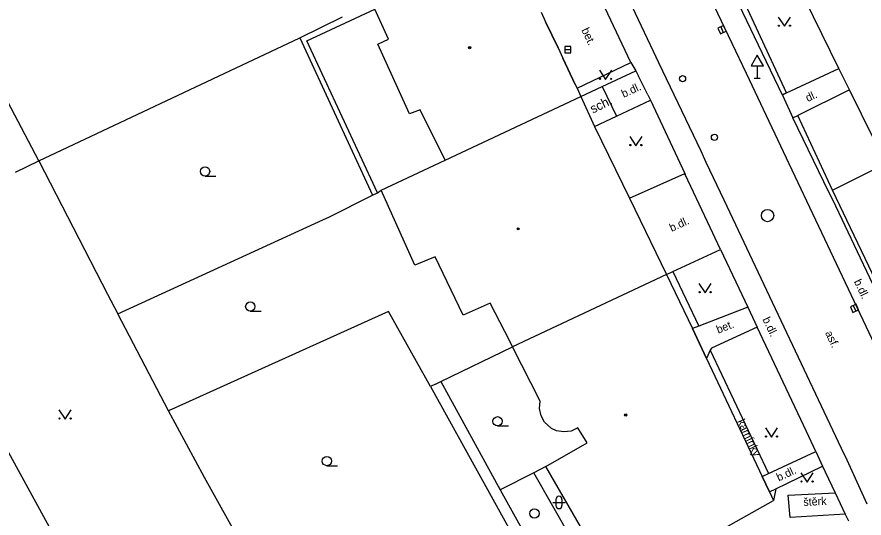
# Model space of a CAD drawing. Extents: x -600391 to -599491, y -1160176 to -1159402.
# Drawn here: x -600232.8 to -600164, y -1159825.7 to -1159785 of the extents above; entities that cross this region are included whole.
import ezdxf

# ---------------------------------------------------------------- set-up
doc = ezdxf.new("R2010")
doc.units = 0
for name, color, linetype in [('Level 10', 7, 'Continuous'), ('Level 11', 7, 'Continuous'), ('Level 27', 7, 'Continuous'), ('Level 28', 7, 'Continuous'), ('Level 34', 7, 'Continuous'), ('Level 36', 7, 'Continuous'), ('Level 39', 7, 'Continuous'), ('Level 40', 7, 'Continuous'), ('Level 42', 7, 'Continuous'), ('Level 5', 7, 'Continuous'), ('Level 51', 7, 'Continuous'), ('Level 6', 7, 'Continuous'), ('Level 7', 7, 'Continuous'), ('Level 8', 7, 'Continuous')]:
    doc.layers.add(name, color=color, linetype=linetype)

msp = doc.modelspace()

# ---------------------------------------------------------------- linework, layer by layer
at = {"layer": 'Level 10'}
for points in [[(-600207.08, -1159733.09), (-600204.09, -1159739.42), (-600203.67, -1159740.35), (-600201.73, -1159744.4), (-600201.28, -1159745.31), (-600193.16, -1159762.47), (-600192.72, -1159763.39), (-600190.15, -1159768.81), (-600189.71, -1159769.71), (-600181.16, -1159787.79), (-600180.73, -1159788.7), (-600177.31, -1159795.87), (-600176.88, -1159796.81), (-600175.437, -1159799.852), (-600174.02, -1159802.84), (-600173.59, -1159803.76), (-600165.9, -1159820.02), (-600165.45, -1159820.96), (-600163.81, -1159824.53)], [(-600158.72, -1159821.06), (-600159.95, -1159818.426), (-600160.27, -1159817.74), (-600169.89, -1159797.44), (-600171.51, -1159794.02), (-600173.6, -1159789.61), (-600177.09, -1159782.26), (-600180.56, -1159774.92), (-600184.38, -1159766.92), (-600187.61, -1159760.14), (-600188.03, -1159759.22), (-600189.21, -1159756.74), (-600189.62, -1159755.83), (-600193.78, -1159747.07), (-600194.22, -1159746.13), (-600195.79, -1159742.84), (-600196.2, -1159741.93), (-600197.21, -1159739.84), (-600197.66, -1159738.93), (-600199.99, -1159733.97)]]:
    msp.add_lwpolyline(points, dxfattribs=at)
at = {"layer": 'Level 11'}
for points in [[(-600182.98, -1159788.7), (-600185.54, -1159783.24)], [(-600187.35, -1159790.8), (-600182.98, -1159788.7)], [(-600170.34, -1159791.18), (-600166.08, -1159789.19)], [(-600185.3, -1159790.66), (-600184.14, -1159793.07)], [(-600165.23, -1159790.93), (-600169.43, -1159793)], [(-600184.14, -1159793.07), (-600181.39, -1159791.77)], [(-600185.92, -1159793.91), (-600184.14, -1159793.07)], [(-600183.09, -1159799.71), (-600178.6, -1159797.73)], [(-600175.69, -1159803.88), (-600176.76, -1159801.63), (-600178.57, -1159797.81)], [(-600175.69, -1159803.88), (-600173.49, -1159808.57)], [(-600179.56, -1159805.67), (-600177.46, -1159810.11)], [(-600173.49, -1159808.57), (-600177.46, -1159810.11), (-600177.98, -1159810.31)], [(-600173.49, -1159808.57), (-600172.72, -1159810.19)], [(-600172.72, -1159810.19), (-600176.44, -1159811.9), (-600176.53, -1159812.07), (-600176.85, -1159812.73)], [(-600167.97, -1159820.27), (-600168.72, -1159818.65), (-600172.72, -1159810.19)], [(-600176.53, -1159812.07), (-600171.8, -1159822.07)], [(-600172.32, -1159822.31), (-600171.8, -1159822.07), (-600167.97, -1159820.27)], [(-600167.97, -1159820.27), (-600167.43, -1159821.46)], [(-600171.73, -1159823.56), (-600171.21, -1159823.31), (-600167.43, -1159821.46)], [(-600167.43, -1159821.46), (-600167.2, -1159821.94), (-600166.39, -1159823.64), (-600165.58, -1159825.36), (-600165.31, -1159825.92)], [(-600171.21, -1159823.31), (-600171.4, -1159824.25)], [(-600165.58, -1159825.36), (-600170.04, -1159825.64), (-600170.2, -1159823.82), (-600166.39, -1159823.64)]]:
    msp.add_lwpolyline(points, dxfattribs=at)
at = {"layer": 'Level 27'}
for p, q in [((-600175.684, -1159785.813), (-600175.476, -1159786.267)), ((-600188.34, -1159787.66), (-600187.84, -1159787.66)), ((-600164.917, -1159808.43), (-600164.723, -1159808.89))]:
    msp.add_line(p, q, dxfattribs=at)
for points in [[(-600175.911, -1159785.917), (-600175.703, -1159786.371), (-600175.249, -1159786.163), (-600175.457, -1159785.709)], [(-600188.34, -1159787.91), (-600187.84, -1159787.91), (-600187.84, -1159787.41), (-600188.34, -1159787.41)], [(-600165.148, -1159808.527), (-600164.953, -1159808.988), (-600164.492, -1159808.793), (-600164.687, -1159808.332)]]:
    msp.add_lwpolyline(points, close=True, dxfattribs=at)
msp.add_circle((-600171.88, -1159801.13), 0.5, dxfattribs=at)
at = {"layer": 'Level 28'}
for centre in [(-600178.78, -1159790.02), (-600176.19, -1159794.78)]:
    msp.add_circle(centre, 0.25, dxfattribs=at)
at = {"layer": 'Level 34'}
for p, q in [((-600172.72, -1159788.972), (-600172.72, -1159789.99)), ((-600172.97, -1159789.99), (-600172.47, -1159789.99))]:
    msp.add_line(p, q, dxfattribs=at)
msp.add_lwpolyline([(-600173.22, -1159788.972), (-600172.22, -1159788.972), (-600172.72, -1159788.106)], close=True, dxfattribs=at)
at = {"layer": 'Level 36'}
for p, q in [((-600217.55, -1159797.925), (-600216.675, -1159797.925)), ((-600213.88, -1159808.895), (-600213.005, -1159808.895)), ((-600193.8, -1159818.205), (-600192.925, -1159818.205)), ((-600207.66, -1159821.435), (-600206.785, -1159821.435)), ((-600189.326, -1159824.416), (-600188.326, -1159824.416)), ((-600189.076, -1159824.166), (-600189.076, -1159824.666)), ((-600188.576, -1159824.166), (-600188.576, -1159824.666))]:
    msp.add_line(p, q, dxfattribs=at)
for points in [[(-600171.01, -1159785.02), (-600170.51, -1159785.77), (-600170.01, -1159785.02)], [(-600185.53, -1159789.33), (-600185.03, -1159790.08), (-600184.53, -1159789.33)], [(-600183.07, -1159794.71), (-600182.57, -1159795.46), (-600182.07, -1159794.71)], [(-600177.45, -1159806.65), (-600176.95, -1159807.4), (-600176.45, -1159806.65)], [(-600229.42, -1159816.9), (-600228.92, -1159817.65), (-600228.42, -1159816.9)], [(-600172.06, -1159818.37), (-600171.56, -1159819.12), (-600171.06, -1159818.37)], [(-600169.17, -1159822.02), (-600168.67, -1159822.77), (-600168.17, -1159822.02)]]:
    msp.add_lwpolyline(points, dxfattribs=at)
for centre, radius in [((-600170.96, -1159785.72), 0.05), ((-600170.061, -1159785.72), 0.05), ((-600185.48, -1159790.03), 0.05), ((-600184.581, -1159790.03), 0.05), ((-600183.02, -1159795.41), 0.05), ((-600182.121, -1159795.41), 0.05), ((-600217.55, -1159797.55), 0.375), ((-600177.4, -1159807.35), 0.05), ((-600176.501, -1159807.35), 0.05), ((-600213.88, -1159808.52), 0.375), ((-600229.37, -1159817.6), 0.05), ((-600228.471, -1159817.6), 0.05), ((-600193.8, -1159817.83), 0.375), ((-600172.01, -1159819.07), 0.05), ((-600171.111, -1159819.07), 0.05), ((-600207.66, -1159821.06), 0.375), ((-600169.12, -1159822.72), 0.05), ((-600168.221, -1159822.72), 0.05), ((-600190.81, -1159825.31), 0.375)]:
    msp.add_circle(centre, radius, dxfattribs=at)
for centre, start, end in [((-600188.826, -1159824.166), 0, 180), ((-600188.826, -1159824.666), 180, 0)]:
    msp.add_arc(centre, 0.25, start, end, dxfattribs=at)
at = {"layer": 'Level 39'}
for centre, radius in [((-600196.07, -1159787.5), 0.09), ((-600196.07, -1159787.5), 0.0398), ((-600192.13, -1159802.21), 0.09), ((-600192.13, -1159802.21), 0.0398), ((-600183.4, -1159817.32), 0.09), ((-600183.4, -1159817.32), 0.0398)]:
    msp.add_circle(centre, radius, dxfattribs=at)
at = {"layer": 'Level 5'}
for points in [[(-600166.08, -1159789.19), (-600170.89, -1159779.39)], [(-600202.67, -1159786.81), (-600203.77, -1159784.37)], [(-600190.27, -1159784.63), (-600189.9, -1159785.41)], [(-600189.9, -1159785.41), (-600188.89, -1159787.51)], [(-600203.52, -1159787.22), (-600202.67, -1159786.81)], [(-600200.94, -1159792.88), (-600203.52, -1159787.22)], [(-600188.89, -1159787.51), (-600188.51, -1159788.36)], [(-600188.51, -1159788.36), (-600187.49, -1159790.5)], [(-600165.23, -1159790.93), (-600166.08, -1159789.19)], [(-600187.49, -1159790.5), (-600187.35, -1159790.8)], [(-600187.35, -1159790.8), (-600187.04, -1159791.48)], [(-600198.06, -1159796.64), (-600187.04, -1159791.48)], [(-600187.04, -1159791.48), (-600185.92, -1159793.91)], [(-600162.28, -1159796.91), (-600165.23, -1159790.93)], [(-600200.09, -1159792.55), (-600200.94, -1159792.88)], [(-600198.06, -1159796.64), (-600200.09, -1159792.55)], [(-600185.92, -1159793.91), (-600183.09, -1159799.71)], [(-600203.26, -1159799.07), (-600198.06, -1159796.64)], [(-600200.52, -1159805.15), (-600203.26, -1159799.07)], [(-600183.09, -1159799.71), (-600180.09, -1159805.92)], [(-600198.88, -1159804.48), (-600200.52, -1159805.15)], [(-600196.59, -1159809.23), (-600198.88, -1159804.48)], [(-600180.09, -1159805.92), (-600192.58, -1159811.78)], [(-600180.09, -1159805.92), (-600177.98, -1159810.31)], [(-600194.39, -1159808.23), (-600196.59, -1159809.23)], [(-600192.81, -1159811.33), (-600194.39, -1159808.23)], [(-600177.98, -1159810.31), (-600176.85, -1159812.73)], [(-600192.58, -1159811.78), (-600192.81, -1159811.33)], [(-600190.33, -1159816.2), (-600192.58, -1159811.78)], [(-600176.85, -1159812.73), (-600172.32, -1159822.31)], [(-600190.39, -1159816.8), (-600190.33, -1159816.2)], [(-600190.27, -1159817.39), (-600190.39, -1159816.8)], [(-600189.98, -1159817.91), (-600190.27, -1159817.39)], [(-600189.43, -1159818.41), (-600189.98, -1159817.91)], [(-600189.01, -1159818.6), (-600189.43, -1159818.41)], [(-600187.28, -1159818.36), (-600187.82, -1159818.62)], [(-600186.52, -1159819.58), (-600187.28, -1159818.36)], [(-600188.42, -1159818.7), (-600189.01, -1159818.6)], [(-600187.82, -1159818.62), (-600188.42, -1159818.7)], [(-600189.89, -1159821.5), (-600186.52, -1159819.58)], [(-600184.14, -1159831.42), (-600189.89, -1159821.5)], [(-600172.32, -1159822.31), (-600171.73, -1159823.56)], [(-600171.73, -1159823.56), (-600171.4, -1159824.25)], [(-600184.14, -1159831.42), (-600171.4, -1159824.25)]]:
    msp.add_lwpolyline(points, dxfattribs=at)
at = {"layer": 'Level 51'}
for points in [[(-600231.06, -1159796.68), (-600238.9, -1159781.79)], [(-600209.28, -1159786.95), (-600203.77, -1159784.37)], [(-600209.86, -1159786.71), (-600206.39, -1159785)], [(-600231.06, -1159796.68), (-600209.86, -1159786.71)], [(-600209.86, -1159786.71), (-600203.96, -1159799.47)], [(-600203.54, -1159799.29), (-600209.28, -1159786.95)], [(-600232.95, -1159797.62), (-600231.06, -1159796.68)], [(-600231.06, -1159796.68), (-600225.47, -1159807.52)], [(-600203.54, -1159799.29), (-600203.26, -1159799.07)], [(-600207.44, -1159801.23), (-600203.96, -1159799.47)], [(-600203.96, -1159799.47), (-600203.54, -1159799.29)], [(-600224.63, -1159809.1), (-600208, -1159801.49)], [(-600208, -1159801.49), (-600207.44, -1159801.23)], [(-600225.47, -1159807.52), (-600224.63, -1159809.1)], [(-600220.53, -1159816.97), (-600224.63, -1159809.1)], [(-600202.67, -1159808.93), (-600220.53, -1159816.97)], [(-600199.25, -1159815.01), (-600202.67, -1159808.93)], [(-600198.42, -1159814.6), (-600192.58, -1159811.78)], [(-600228.91, -1159828.75), (-600236.99, -1159814.01)], [(-600198.85, -1159814.83), (-600199.25, -1159815.01)], [(-600198.85, -1159814.83), (-600198.42, -1159814.6)], [(-600198.42, -1159814.6), (-600193.6, -1159823.39)], [(-600199.25, -1159815.01), (-600190.53, -1159830.76)], [(-600217.61, -1159822.39), (-600220.53, -1159816.97)], [(-600189.89, -1159821.5), (-600190.85, -1159822.02)], [(-600211.3, -1159833.74), (-600217.61, -1159822.39)], [(-600190.85, -1159822.02), (-600193.6, -1159823.39)], [(-600187.78, -1159827.42), (-600190.85, -1159822.02)], [(-600193.6, -1159823.39), (-600190.5, -1159828.94)]]:
    msp.add_lwpolyline(points, dxfattribs=at)
at = {"layer": 'Level 6'}
for points in [[(-600188.89, -1159787.51), (-600189.9, -1159785.41)], [(-600187.49, -1159790.5), (-600188.51, -1159788.36)], [(-600176.85, -1159812.73), (-600177.98, -1159810.31)], [(-600171.73, -1159823.56), (-600172.32, -1159822.31)]]:
    msp.add_lwpolyline(points, dxfattribs=at)
at = {"layer": 'Level 7'}
for points in [[(-600170.34, -1159791.18), (-600174.9, -1159781.36), (-600173.01, -1159780.43)], [(-600170.34, -1159791.18), (-600170.67, -1159791.35), (-600175.52, -1159781.23)], [(-600182.98, -1159788.7), (-600182.58, -1159789.38)], [(-600185.3, -1159790.66), (-600182.58, -1159789.38)], [(-600182.58, -1159789.38), (-600182.36, -1159789.81)], [(-600187.04, -1159791.48), (-600185.3, -1159790.66)], [(-600181.6, -1159791.33), (-600181.39, -1159791.77)], [(-600181.39, -1159791.77), (-600178.6, -1159797.73)], [(-600166.9, -1159799.22), (-600169.82, -1159793.19), (-600169.43, -1159793)], [(-600166.61, -1159799.07), (-600169.43, -1159793)], [(-600166.61, -1159799.07), (-600162.28, -1159796.91)], [(-600178.6, -1159797.73), (-600178.57, -1159797.81)], [(-600143.85, -1159808.66), (-600141.75, -1159812.72), (-600142.08, -1159812.9), (-600142.96, -1159813.39), (-600155.97, -1159820.61), (-600156.16, -1159820.67), (-600156.33, -1159820.59), (-600166.61, -1159799.07)], [(-600155.88, -1159821.2), (-600156.11, -1159821.25), (-600156.3, -1159821.21), (-600156.47, -1159821.1), (-600156.58, -1159820.94), (-600158.15, -1159817.65), (-600158.58, -1159816.75), (-600166.59, -1159799.86), (-600166.9, -1159799.22)], [(-600180.09, -1159805.92), (-600179.56, -1159805.67), (-600175.69, -1159803.88)]]:
    msp.add_lwpolyline(points, dxfattribs=at)
at = {"layer": 'Level 8'}
for points in [[(-600181.6, -1159791.33), (-600182.36, -1159789.81)], [(-600170.67, -1159791.35), (-600169.82, -1159793.19)]]:
    msp.add_lwpolyline(points, dxfattribs=at)

# ---------------------------------------------------------------- texts
at = {"layer": 'Level 40'}
for s, rotation, p in [('bet.', 295.48, (-600187.01, -1159786.07)), ('b.dl.', 24.38, (-600183.57, -1159791.58)), ('dl.', 25.15616, (-600168.61, -1159791.92)), ('b.dl.', 24.38, (-600179.67, -1159802.46)), ('b.dl. ', 295.37, (-600164.89, -1159806.48)), ('b.dl. ', 295.31, (-600172.31, -1159809.55)), ('bet.', 21.18, (-600175.89, -1159810.72)), ('asf.', 295, (-600167.22, -1159810.66)), ('kamínky', 295, (-600174.35, -1159817.83)), ('b.dl. ', 25.14, (-600170.97, -1159822.72)), ('štěrk', 3, (-600168.96, -1159824.71))]:
    msp.add_text(s, height=0.65, rotation=rotation, dxfattribs=at).set_placement(p)
at = {"layer": 'Level 42'}
msp.add_text('sch.', height=0.75, rotation=26, dxfattribs=at).set_placement((-600186.07, -1159792.86))

doc.saveas('drawing.dxf')
